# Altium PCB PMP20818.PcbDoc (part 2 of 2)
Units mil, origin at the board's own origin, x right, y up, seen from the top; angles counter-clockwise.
Board outline 3200 x 3200 mil, 4 copper layers (Top Layer, Signal Layer 1, Signal Layer 2, Bottom Layer), stack 61.2 mil thick; 130 components, 48 nets, 295 pads, 106 vias.
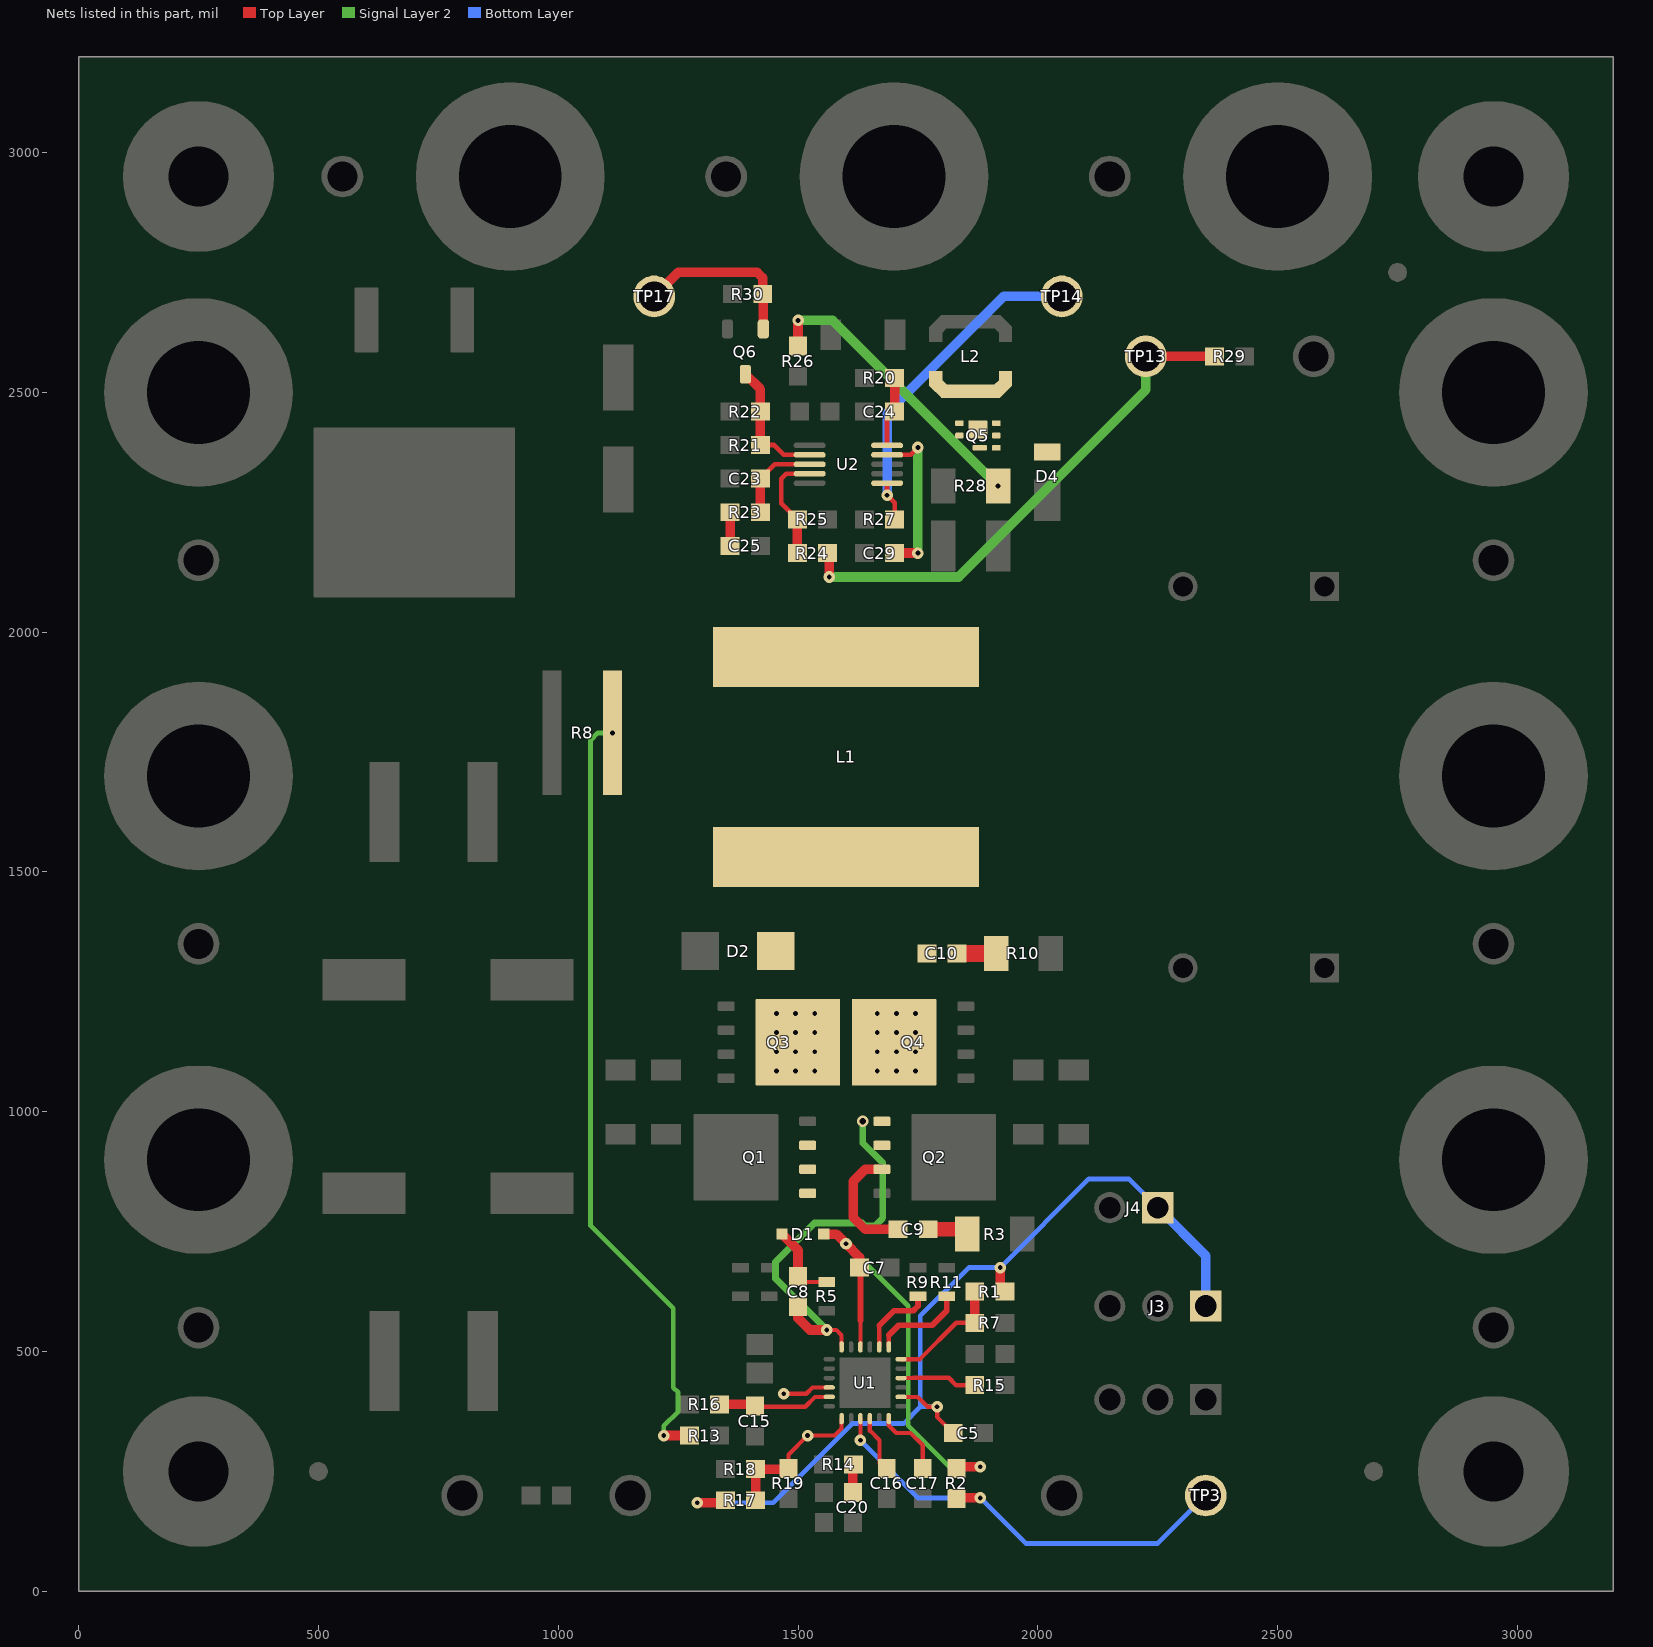
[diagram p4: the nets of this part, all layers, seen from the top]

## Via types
v1: diameter 24, hole 10, Top Layer to Bottom Layer, 69 vias
v2: diameter 24, hole 10, Top Layer to Bottom Layer, tented both sides, 27 vias
v3: diameter 24, hole 14, Top Layer to Bottom Layer, 5 vias
v4: diameter 20, hole 10, Top Layer to Bottom Layer, 5 vias

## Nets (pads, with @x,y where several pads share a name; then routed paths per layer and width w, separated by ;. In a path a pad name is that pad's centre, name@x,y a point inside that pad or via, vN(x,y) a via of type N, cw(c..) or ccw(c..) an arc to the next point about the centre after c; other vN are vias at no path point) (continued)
LO: R9.1 U1.8 | length 162
  Top Layer w9: U1.8@1669.53,509.8 1669.53,554.53
  Top Layer w12: 1669.53,554.53 1700,585 1740,585 1750,595 R9.1@1750,615
LOL: R11.2 U1.7 | length 196.2
  Top Layer w9: U1.7@1689.21,509.8 1689.21,534.21
  Top Layer w12: 1689.21,534.21 1710,555 1780,555 1810,585 R11.2@1810,615
NetC8_1: C8.1 D1.1 R5.2 | length 167.1
  Top Layer w9: C8.1@1500,656.5 1511.5,645 R5.2@1560,645
  Top Layer w20: D1.1@1466.69,745 1500,711.69 C8.1@1500,656.5
NetC9_1: C9.1 R3.1 | length 85.6
  Top Layer w30: C9.1@1771.5,755 1842.91,755 R3.1@1852.91,745
NetC10_2: C10.2 R10.2 | length 85.6
  Top Layer w35: C10.2@1834.43,1330 R10.2@1912.91,1330 ; R10.2@1902.91,1330 R10.2@1907.91,1335
NetC20_1: C20.1 R14.1 | length 57
  Top Layer w20: C20.1@1614.45,206.5 R14.1@1614.45,263.5
NetC23_1: C23.1 R23.2 U2.3 | length 185.2
  Top Layer w10: C23.1@1421.5,2320 1451.5,2350 U2.3@1524.29,2350
  Top Layer w20: R23.2@1421.5,2250 C23.1@1421.5,2320
NetC24_1: C24.1 R20.1 U2.10 | length 147.2
  Top Layer w10: U2.10@1685.71,2389.37 1685.71,2444.21 C24.1@1701.5,2460
  Top Layer w20: C24.1@1701.5,2460 R20.1@1701.5,2530
NetC25_1: C25.1 R23.1 | length 70
  Top Layer w20: C25.1@1358.5,2180 R23.1@1358.5,2250
NetD4_2: D4.2 L2.2 Q5.1 Q5.2 Q5.5 Q5.6 Q5.8
NetL1_2: L1.2 R8.1 R13.2 | length 1643.4
  Top Layer w20: v2(1220,325) R13.2@1273.5,325
  Signal Layer 2 w10: v1(1112.99,1790) 1082.37,1790 1067.37,1775 1067.37,762.63 1240,590 1240,425 1250,415 1250,375 1220,345 v2(1220,325)
NetQ5_4: Q5.4 Q5.7 R26.2 R28.2 | length 613.5
  Top Layer w20: R26.2@1500,2596.5 v2(1500,2650)
  Signal Layer 2 w20: v2(1500,2650) 1572.09,2650 v2(1917.09,2305)
NetQ6_1: Q6.1 R30.2 TP17.1 | length 357
  Top Layer w20: TP17.1@1200,2700 1250,2750 1415,2750 1426.5,2738.5 R30.2@1426.5,2705 ; Q6.1@1427.72,2632.24 R30.2@1427.72,2703.78
NetR17_2: R17.2 R18.1 R19.2 U1.19 | length 316.6
  Top Layer w9: R19.2@1478.5,255 R19.2@1480,256.5 1480,285 v2(1520,325) 1576.14,325 1590.79,339.65 U1.19@1590.79,360.2
  Top Layer w20: R17.2@1411.5,190 R18.1@1411.5,255 R19.2@1478.5,255
NetR24_1: R24.1 R29.2 TP13.1 | length 1086.5
  Top Layer w20: R24.1@1561.5,2165 1565,2161.5 v2(1565,2115) ; TP13.1@2225,2575 R29.2@2368.5,2575
  Signal Layer 2 w20: v2(1565,2115) 1835,2115 2225,2505 TP13.1@2225,2575
NetR24_2: R24.2 R25.2 U2.4 | length 232.4
  Top Layer w10: R25.2@1498.5,2235 1465,2268.5 1465,2320 1475.32,2330.32 U2.4@1524.29,2330.32
  Top Layer w20: R24.2@1498.5,2165 R25.2@1498.5,2235
OSC: R1.2 R7.1 U1.6 | length 250.1
  Top Layer w9: U1.6@1714.8,484.21 1754.21,484.21 1830,560 R7.1@1868.5,560
  Top Layer w20: R7.1@1868.5,560 R1.2@1868.5,625
PG: R2.2 TP3.1 U1.21 | length 946.4
  Top Layer w9: v2(1630,315) 1630,325 1630.16,325.16 U1.21@1630.16,360.2
  Top Layer w20: R2.2@1830,193.5 1831.5,195 v2(1880,195)
  Bottom Layer w10: v2(1630,315) 1750,195 v2(1880,195) 1975,100 2250,100 TP3.1@2350,200
RES: C17.1 U1.24 | length 150.6
  Top Layer w9: U1.24@1689.21,360.2 1689.21,345.79 1704.63,330.37 1734.63,330.37 1760,305 C17.1@1760,256.5
RT: R15.2 U1.4 | length 186.4
  Top Layer w9: U1.4@1714.8,444.84 1740,444.84 ; 1745.16,444.84 1740,444.84 ; R15.2@1853.5,444.84 R15.2@1868.35,430 1829.66,430 1814.13,445.53 1740.69,445.53 1740,444.84
SS: C16.1 U1.22 | length 116.2
  Top Layer w9: U1.22@1649.84,360.2 1649.84,335.16 1670,315 1670,266.5 C16.1@1680,256.5
SW: C8.2 C9.2 C10.1 D2.1 L1.1 Q1.1 Q1.2 Q1.3 Q2.1 Q2.2 Q2.3 Q3.5 Q3.6 Q3.7 Q3.8 Q3.9@1499.57,1145 Q4.5 Q4.6 Q4.7 Q4.8 Q4.9@1700.43,1145 U1.12 | length 1074.5
  Top Layer w9: v2(1560,545) 1580,545 1590.79,534.21 U1.12@1590.79,509.8
  Top Layer w20: C8.2@1500,593.5 1500,570.02 1525.02,545 v2(1560,545) ; Q2.3@1674.96,880 1640,880 1615,855 1615,780 1640,755 C9.2@1708.5,755
  Signal Layer 2 w14: v2(1560,545) 1452.91,652.09 1452.91,686.97 1534.06,768.13 1633.87,768.13 1639.87,762.13 1660.13,762.13 1676.87,778.87 1676.87,893.13 1635,935 v3(1635,980)
  other v1: 1455,1085 1495,1085 1535,1085 1665,1085 1705,1085 1745,1085 1455,1125 1495,1125 1535,1125 1665,1125 1705,1125 1745,1125 1455,1165 1495,1165 1535,1165 1665,1165 1705,1165 1745,1165 1455,1205 1495,1205 1535,1205 1665,1205 1705,1205 1745,1205
SYNC: R27.1 TP14.1 U2.6 | length 718.6
  Top Layer w10: U2.6@1685.71,2310.63 v2(1685.71,2285.49) 1701.5,2269.7 R27.1@1701.5,2235
  Bottom Layer w20: v2(1685.71,2285.49) 1685.71,2457.01 1928.7,2700 TP14.1@2050,2700
UVLO: Q6.3 R21.1 R22.2 U2.2 | length 271.9
  Top Layer w10: R21.1@1421.5,2390 1450,2390 1470.31,2369.69 U2.2@1524.29,2369.69
  Top Layer w20: Q6.3@1390.31,2537.76 1421.5,2506.57 R22.2@1421.5,2460 R21.1@1421.5,2390
VCC: C7.2 D1.2 R2.1 U1.10 | length 953.2
  Top Layer w9: U1.10@1630.16,509.8 1630.16,564.84
  Top Layer w12: C7.2@1628.5,675 1630.16,673.35 1630.16,564.84
  Top Layer w20: D1.2@1553.31,745 1580,745 v2(1600,725) 1628.5,696.5 C7.2@1628.5,675 ; R2.1@1830,256.5 1833.5,260 v2(1880,260)
  Signal Layer 2 w10: v2(1600,725) 1730,595 1730,345 1815,260 v2(1880,260)
VCC1: C29.1 U2.9 | length 339.1
  Top Layer w10: U2.9@1685.71,2369.69 1734.69,2369.69 v2(1750,2385)
  Top Layer w20: C29.1@1701.5,2165 v2(1750,2165)
  Signal Layer 2 w20: v2(1750,2165) v2(1750,2385)
VCCX: U1.16 | length 107.9
  Top Layer w9: v2@1473,412 1470,415 v2(1470,411.87) 1516.87,411.87 ; 1517,412 1530.16,425.16 U1.16@1565.2,425.16
VDDA: C5.2 J3.1 J4.1 R1.1 R17.1 U1.2 | length 1924
  Top Layer w9: U1.2@1714.8,405.47 1749.53,405.47 1770,385 v2(1790,385) 1790,363.5 C5.2@1823.5,330 ; R1.1@1921.5,635 R1.1@1931.5,625
  Top Layer w20: v1(1290,185) 1343.5,185 R17.1@1348.5,190 ; R1.1@1921.5,635 v2(1921.5,675)
  Bottom Layer w10: v1(1290,185) 1447.95,185 1612.95,350 1720,350 1755,385 ; v2(1790,385) 1755,385 ; J4.1@2250,800 2190,860 2106.5,860 v2(1921.5,675) 1855.75,675 1755,574.25 1755,385
  Bottom Layer w20: J4.1@2250,800 2350,700 J3.1@2350,595
VO_IC: C15.1 R16.1 U1.17 | length 235.4
  Top Layer w9: C15.1@1410,396.5 1421.5,385 1515,385 1535.47,405.47 U1.17@1565.2,405.47
  Top Layer w20: R16.1@1336.5,390 C15.1@1403.5,390
pads on no net: FID1.1 FID2.1 FID3.1 H1.1 H2.1 H3.1 H4.1 LBL1.0 Q1.9@1354.88,847.91 Q1.9@1354.88,905 Q1.9@1354.88,962.09 Q1.9@1388.35,905 Q1.9@1424.96,847.91 Q1.9@1424.96,905 Q1.9@1424.96,962.09 Q2.9@1770.04,847.91 Q2.9@1770.04,905 Q2.9@1770.04,962.09 Q2.9@1806.65,905 Q2.9@1840.12,847.91 Q2.9@1840.12,905 Q2.9@1840.12,962.09 Q3.9@1445.04,1087.91 Q3.9@1445.04,1145 Q3.9@1445.04,1202.09 Q3.9@1481.65,1145 Q3.9@1515.12,1087.91 Q3.9@1515.12,1145 Q3.9@1515.12,1202.09 Q4.9@1684.88,1087.91 Q4.9@1684.88,1145 Q4.9@1684.88,1202.09 Q4.9@1718.35,1145 Q4.9@1754.96,1087.91 Q4.9@1754.96,1145 Q4.9@1754.96,1202.09 Q5.0

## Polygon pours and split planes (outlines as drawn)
50VIN on Signal Layer 2 "Signal Layer2-VIN" (solid, remove dead copper, pour order 168): 2265,1005 2265,837.73 1785,837.73 1785,1005
50VIN on Signal Layer 2 "Signal Layer2-VIN" (solid, remove dead copper, pour order 166): 1455,1005 1455,835.84 1080,835.84 1080,1005
SW on Signal Layer 2 "SignalLayer2-SW" (solid, remove dead copper, pour order 170): 1791.2,1245 1791.2,1075 1406.2,1075 1406.2,1245
GND on Signal Layer 2 "Signal Layer2-GND" (solid, pour order 172): 0,3200 0,0 3200,0 3200,3200
50VIN on Signal Layer 1 "Signal Layer1-VIN" (solid, remove dead copper, pour order 160): 2280,1010 2280,835 1075,835 1075,1010
GND on Signal Layer 1 "Signal Layer1-GND" (solid, pour order 164): 0,3200 0,0 3200,0 3200,3200
SW on Signal Layer 1 "SignalLayer1-SW" (solid, remove dead copper, pour order 162): 1792.5,1230 1792.5,1060 1407.5,1060 1407.5,1230
12VS on Bottom Layer "12VS_L04_P174" (solid, remove dead copper, pour order 174): 1200,3200 1200,2705 450,2705 450,3200
50VIN on Bottom Layer "50VIN_L04_P180" (solid, remove dead copper, pour order 180): 2700,1950 3200,1950 3200,1170 2700,1170
50VOUT on Bottom Layer "50VOUT_L04_P182" (solid, remove dead copper, pour order 182): 2698.75,2750 3198.75,2750 3198.75,1970 2698.75,1970
11VOUT on Bottom Layer "11VOUT_L04_P178" (solid, remove dead copper, pour order 178): 0,1950 500,1950 500,1200 0,1200
12VIN on Bottom Layer "12VIN_L04_P176" (solid, remove dead copper, pour order 176): 0,2750 326.38,2750 500,2576.38 500,1970 0,1970
GND on Bottom Layer "Bottom Layer-GND" (solid, pour order 188): 0,3200 0,0 3200,0 3200,3200
SW on Bottom Layer "BottomLayer-SW" (solid, remove dead copper, pour order 186): 1792.5,1240 1792.5,1060 1407.5,1060 1407.5,1240
50VIN on Bottom Layer "BottomLayer-Vin" (solid, remove dead copper, pour order 184): 1080,1020 1080,835 1740,835 2125,835 2125,1020
50VIN on Top Layer "50VIN_L01_P092" (solid, remove dead copper, pour order 92): 1466.3,1009.68 1466.3,806.57 1062.24,806.88 1062.24,1009.47 1062.76,1010
50VIN on Top Layer "50VIN_L01_P084" (solid, remove dead copper, pour order 84): 3200,2020 2720,2020 2700,2000 2700,1280 2625,1205 2505,1205 2405,1205 2310,1110 2190,990 2190,860 2605,860 2680,935 2945,1200 3200,1200
11VOUT on Top Layer "11VOUT_L01_P080" (solid, remove dead copper, pour order 80): 0,1980 1050,1980 1050,350 750,350 750,1765 500,1765 500,1400 350,1250 0,1250
12VS on Top Layer "12VS_L01_P069" (solid, remove dead copper, pour order 69): 450,3200 1125,3200 1125,2860 835,2570 585,2570 450,2705
12VIN on Top Layer "12VIN_L01_P076" (solid, remove dead copper, pour order 76): 0,2750 325,2750 498.62,2576.38 498.62,2506.38 498.62,2500 950,2500 950,2450 995.07,2404.93 995.07,2399.99 1260,2399.99 1260,2210 1050,2000 0,2000
50VOUT on Top Layer "50VOUT_L01_P086" (solid, remove dead copper, pour order 86): 1865,2240 1975,2240 1975,2325 2090,2325 2200,2325 2410,2535 2410,2685 3175,2685 3200,2685 3200,2050 3195,2045 2700,2045 2675,2020 2675,1280 2620,1225 2525,1225 2525,2020 2370,2175 2160,2175 2105,2120 1865,2120 1865,2242.99
NetQ5_4 on Top Layer "NETQ5_4_L01_P094" (solid, remove dead copper, pour order 94): 1865,2390 1950,2390 1950,2258.74 1865,2258.74
NetD4_2 on Top Layer "NETD4_2_L01_P096" (solid, remove dead copper, pour order 96): 1750,2560 1965,2560 2065,2460 2065,2345 1970,2345 1970,2405 1790,2405 1750,2445
12VIN on Top Layer "12VIN_L01_P078" (solid, remove dead copper, pour order 78): 1630,2700 1960,2700 1960,2585 1920,2585 1630,2585 1630,2657.4
50VIN on Top Layer "Top Layer-VIN" (solid, remove dead copper, pour order 110): 1725.63,1010 2280,1010 2280,835 2185,835 2080,730 2071.58,721.58 1939.52,721.58 1939.93,810 1725.63,810
GND on Top Layer "Top Layer-GND" (solid, remove dead copper, pour order 158): 0,3200 0,0 3200,0 3200,3200
SW on Top Layer "SW_L01_P104" (solid, remove dead copper, pour order 104): 2010,1625 2010,1400 1785,1400 1785,1025 1700,1025 1700,815 1495,815 1495,1025 1415,1025 1415,1400 1190,1400 1190,1625
NetL1_2 on Top Layer "NETL1_2_L01_P106" (solid, remove dead copper, pour order 106): 2010,2090 1175,2090 1065,1980 1065,1650 2010,1650

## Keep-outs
Keep-Out Layer:
  the board outline again, w7
  text ".Layer_Name" at 577,-858.49 h60

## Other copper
Top Layer:
  text ".Layer_Name" at 577,-858.49 h60
Signal Layer 1:
  text ".layer_Name" at 577,-858.49 h40
Signal Layer 2:
  text ".layer_Name" at 577,-858.49 h40
Bottom Layer:
  rectangle net 50VOUT: 2525,1980 3050,2200
  rectangle net 50VOUT: 2525,1200 2670,2200
  text ".Layer_Name" at 577,-858.49 h60

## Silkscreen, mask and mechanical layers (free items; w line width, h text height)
Top Overlay:
  region: 1305,119.99 1005,119.99 1005,19.99 1305,19.99
  text "-" at 950,44.99 h40
  text ".PRJ_Number" at 380,39.99 h60
  text ".PCB_Rev" at 875,40 h60
  text ".Layer_Name" at 577,-858.49 h60
Bottom Overlay:
  text ".Layer_Name" at 577,-858.49 h60
Top Paste:
  text ".Layer_Name" at 577,-858.49 h60
Bottom Paste:
  text ".Layer_Name" at 577,-858.49 h60
Top Solder:
  text ".Layer_Name" at 577,-858.49 h60
  text ".Layer_Name" at 577,-858.49 h60
Bottom Solder:
  text ".Layer_Name" at 577,-858.49 h60
Drill Guide:
  text ".Layer_Name" at 577,-858.49 h60
M1 Board Outline:
  the board outline again, w10
  text ".Layer_Name" at 577,-858.49 h60
M2 Board Dimensions:
  rectangle: 0,-275 125,-150
  rectangle: 125,-400 500,-275
  lines w7: 0,-275 1000,-275 ; 125,-400 125,-150 ; 250,-400 250,-150 ; 500,-400 500,-150 ; 750,-400 750,-150 ; 0,-400 1000,-400 1000,-150 0,-150 0,-400
  text ".Layer_Name" at 577,-858.49 h60
M3 3D STEP Top:
  text ".Layer_Name" at 577,-858.49 h60
M4 3D STEP Bottom:
  text ".Layer_Name" at 577,-858.49 h60
M5 Assembly Top:
  lines w10: -292,-930.17 6308,-930.17 ; -292,-726.83 6310,-726.83 ; -292,-523.5 -292,-1133.5 3713,-1133.5 6310,-1133.5 6310,-523.5 -291.5,-523.5 -291.5,-1133.5 1284,-1133.5 ; 2173,-1133.5 2173,-523.5 ; 3440,-726.83 3440,-523.5 ; 4280,-726.83 4280,-523.5 ; 4902,-1140 4902,-937.17
  text "COMPONENTS MARKED 'DNP' SHOULD NOT BE POPULATED." at 1153.5,-318.5 h40
  text "ASSEMBLY VARIANT:" at 1153,-434 h40
  text ".VariantName" at 2189,-434 h40
  text "PCB VIEWED FROM TOP SIDE" at -228.5,-655.67 h60
  text "BOARD #:" at 2248,-655.67 h60
  text ".PRJ_Number" at 2793.5,-655.67 h60
  text "REV:" at 3638,-655.67 h60
  text ".PCB_Rev" at 3929.5,-655.67 h60
  text "SVN REV:" at 4476,-655.67 h60
  text ".VersionControl_RevNumber" at 4982,-655.67 h60
  text "TID #:" at 2248,-859 h60
  text ".TID" at 2793.5,-859 h60
  text "PLOT NAME =" at -228.5,-1064.34 h60
  text ".plot_File_Name" at 577,-1064.34 h60
  text "GENERATED    :" at 2250,-1064.34 h60
  text ".Print_Date" at 3119.5,-1064.34 h60
  text ".Print_Time" at 3848.5,-1064.34 h60
  text "TEXAS INSTRUMENTS" at 5113,-1064.34 h60
M6 Assembly Bottom:
  lines w10: -292.5,-727.33 6309.5,-727.33 ; -290.5,-930.67 6309.5,-930.67 ; 1115.5,-1140.5 1115.5,-937.67 ; 1737.5,-727.33 1737.5,-524 ; 2577.5,-727.33 2577.5,-524 ; 3844.5,-1134 3844.5,-524 ; 4733.5,-1134 6309,-1134 6309,-524 -292.5,-524 -292.5,-1134 2304.5,-1134 6309.5,-1134 6309.5,-524
  text "COMPONENTS MARKED 'DNP' SHOULD NOT BE POPULATED." at 6102,-318 h40
  text ".VariantName" at 5058,-434 h40
  text "ASSEMBLY VARIANT:" at 6097,-434 h40
  text ".VersionControl_RevNumber" at 1035.5,-656.17 h60
  text "SVN REV:" at 1541.5,-656.17 h60
  text ".PCB_Rev" at 2088,-656.17 h60
  text "REV:" at 2379.5,-656.17 h60
  text ".PRJ_Number" at 3224,-656.17 h60
  text "BOARD #:" at 3769.5,-656.17 h60
  text "PCB VIEWED FROM BOTTOM SIDE" at 6246,-656.17 h60
  text ".TID" at 3224,-859.5 h60
  text "TID #:" at 3769.5,-859.5 h60
  text "TEXAS INSTRUMENTS" at 904.5,-1064.84 h60
  text ".Print_Time" at 2169,-1064.84 h60
  text ".Print_Date" at 2898,-1064.84 h60
  text "GENERATED    :" at 3767.5,-1064.84 h60
  text ".plot_File_Name" at 5440.5,-1064.84 h60
  text "PLOT NAME =" at 6246,-1064.84 h60
M9 Title Sheet:
  drawing of 57 lines, arcs and shapes, not listed
  text "1" at 739.84,8036.5 h70
  text "2" at 3235.5,8036.5 h70
  text "3" at 5724.84,8036.5 h70
  text "4" at 8231.51,8036.5 h70
  text "5" at 10730.5,8036.5 h70
  text "6" at 13235.5,8036.5 h70
  text "A" at -416.5,6893.5 h70
  text "A" at 14383.5,6893.5 h70
  text "B" at -416.5,4513.5 h70
  text "B" at 14383.5,4513.5 h70
  text "C" at -416.5,2138.5 h70
  text "C" at 14383.5,2138.5 h70
  text "PROJECT TITLE:" at 11343.5,277.5 h45
  text ".PRJ_Title" at 11393.5,144.17 h70
  text "DESIGNED FOR:" at 11343.5,-23.5 h45
  text ".PRJ_Customer" at 11393.5,-163.5 h70
  text "D" at -416.5,-231.5 h70
  text "D" at 14383.5,-231.5 h70
  text "FILE NAME:" at 11343.5,-323.5 h45
  text ".PCB_File_Name_No_Path" at 11393.5,-443.5 h70
  text "Texas Instruments (TI) and/or its licensors do not warrant the accuracy or completeness of this specification" at 6374,-605.34 h45
  text "ENGINEER:" at 11343.5,-613.5 h45
  text "LAYOUT BY:" at 12848.5,-613.5 h45
  text "or any information contained therein. TI and/or its licensors do not warrant that this design will meet" at 6329.01,-718 h45
  text ".PRJ_Engineer" at 11393.5,-768.49 h70
  text ".PCB_Layout" at 12899,-768.49 h70
  text "the specifications, will be suitable for your application or fit for any particular purpose, or will operate in" at 6329.01,-830.67 h45
  text ".Layer_Name" at 577,-858.49 h60
  text "ALTIUM DESIGNER VERSION:" at 12848.5,-923.5 h45
  text "an implementation. TI and/or its licensors do not warrant that the design is production worthy. You should" at 6329.01,-943.33 h45
  text "completely validate and test your design implementation to confirm the system functionality for your application." at 6374,-1056 h45
  text ".print_Scale" at 11393.5,-1056.83 h70
  text ".Application_BuildNumber" at 12899,-1056.83 h70
  text "1" at 739.84,-1263.5 h70
  text "2" at 3235.5,-1263.5 h70
  text "3" at 5724.84,-1263.5 h70
  text "4" at 8231.51,-1263.5 h70
  text "5" at 10730.5,-1263.5 h70
  text "6" at 13235.5,-1263.5 h70
M10 Fab Notes:
  drawing of 185 lines, arcs and shapes, not listed
  text "DESIGN INFORMATION" at 12381.02,5910 h60
  text "MIN. TRACK WIDTH:" at 11736.46,5730 h60
  text "8" at 12832.7,5730 h60
  text "MIL" at 12987.46,5730 h60
  text "MIN. CLEARANCE:" at 11736.46,5598 h60
  text "0.2" at 12772.7,5598 h60
  text "mm" at 12987.46,5598 h60
  text "MIN. VIA PAD SIZE:" at 11736.46,5466 h60
  text "24" at 12802.71,5466 h60
  text "MIL" at 12987.46,5466 h60
  text "0.152mm (6MIL)" at 12431.46,5324.29 h60
  text "MINIMUM ANNULAR RING" at 11407.23,5320 h60
  text "EXTERNAL" at 13139.46,5320 h60
  text "PER" at 11607.23,5202 h60
  text "IPC-D-275 CLASS 2 LEVEL C" at 11827.23,5202 h60
  text "MIL, HOLES" at 13315.46,5089.71 h60
  text "+/-" at 12923,5089 h60
  text "+/-" at 13777,5089 h60
  text "REGISTRATION TOLERANCES:" at 11407.23,5084 h60
  text "METAL" at 12607,5084 h60
  text "5" at 13183.2,5084 h60
  text "3" at 14016.2,5084 h60
  text "MIL" at 14132.46,5084 h60
  text "MATERIAL:" at 11332.46,4874.54 h60
  text "FR-4 High Tg" at 12318.9,4734.21 h60
  text "FR-408" at 11753.46,4725.64 h60
  text "X" at 12165.46,4725.64 h60
  text "OTHER" at 13241.46,4725.64 h60
  text "62 MIL (1.6mm) +/-10%" at 12073.56,4562.92 h60
  text "THICKNESS:" at 11407.23,4558.64 h60
  text "X" at 11945.4,4558.64 h60
  text "OTHER" at 13358.46,4558.64 h60
  text "TOLERANCE:" at 11407.23,4400.64 h60
  text "X" at 12246.53,4400.64 h60
  text "ANSI IPC-6012 TYPE 3 CLASS 2" at 12433.48,4400.64 h60
  text "OTHER +/-" at 12433.46,4244.64 h60
  text "BOW & TWIST:" at 11407.23,4087.64 h60
  text "X" at 12246.53,4087.64 h60
  text "ANSI IPC-6012 TYPE 3 CLASS 2" at 12433.48,4087.64 h60
  text "OTHER +/-" at 12433.46,3929.13 h60
  text "DRILLING:" at 11332.46,3790.64 h60
  text "REFERENCE:" at 11407.23,3673.64 h60
  text "X" at 12055.46,3673.64 h60
  text "AS SHOWN" at 12242.46,3673.64 h60
  text "X" at 12956.46,3673.64 h60
  text "NC_DRILL FILES" at 13093.46,3673.64 h60
  text "PTH MIN COPPER THICKNESS:" at 11407.23,3515.64 h60
  text "X" at 12757.46,3515.64 h60
  text "1MIL" at 12894.46,3515.64 h60
  text "OTHER" at 13391.46,3515.64 h60
  text "BOARD FINISH:" at 11332.46,3356.64 h60
  text "SILKSCREEN:" at 11487.68,3238.64 h60
  text "X" at 12436.46,3238.64 h60
  text "TOP" at 12562.46,3238.64 h60
  text "X" at 12946.46,3238.64 h60
  text "BOTTOM" at 13073.46,3238.64 h60
  text "SILKSCREEN COLOR:" at 11487.68,3071.64 h60
  text "X" at 12435.42,3071.64 h60
  text "WHITE" at 12562.46,3071.64 h60
  text "OTHER" at 13073.46,3071.64 h60
  text "SOLDER RESIST COLOR:" at 11487.68,2901.64 h60
  text "X" at 12055.42,2742.44 h60
  text "GREEN" at 12182.46,2742.44 h60
  text "BLUE" at 12773.46,2742.44 h60
  text "OTHER" at 13311.46,2742.44 h60
  text "IMMERSION GOLD (ENIG)" at 12393.46,2553.92 h60
  text "ENEPIG" at 13731,2550.64 h60
  text "SURFACE FINISH:" at 11332.46,2549.64 h60
  text "X" at 12206.51,2549.64 h60
  text "IMM. TIN/SILVER OR EQUIV" at 11662,2392.64 h60
  text "OTHER" at 13093.46,2392.64 h60
  text "ARRAY/PANEL:" at 11332.46,2213.64 h60
  text "CUT AND TRIM PER MECH LAYER 1" at 12393.46,2209.35 h60
  text "X" at 12205,2205 h60
  text "N.C. ROUTE" at 12393.46,2057.64 h60
  text "V. SCORE" at 13259.46,2057.64 h60
  text "CERTIFICATION:" at 11332.46,1920.64 h60
  text "MATERIALS AND WORKMANSHIP FOR ALL PCBS" at 12057.46,1920.64 h60
  text "TO MEET OR EXCEED THE REQUIREMENTS OF:" at 12057.46,1822.64 h60
  text "X" at 11683.96,1686.13 h60
  text "ANSI IPC-A-600F CLASS ->" at 11822.96,1686.13 h60
  text "X" at 13462.02,1686.13 h60
  text "2" at 13580.96,1686.14 h60
  text "1" at 13265.96,1684.64 h60
  text "3" at 13934.96,1684.64 h60
  text "X" at 11686.02,1526.64 h60
  text "UL 94V-0" at 11822.96,1526.64 h60
  text "X" at 12498.02,1526.64 h60
  text "RoHS" at 12634.96,1526.64 h60
  text "OTHER" at 13279.36,1526.64 h60
  text "PER ORDER" at 13676.42,1526.64 h60
  text "ADDITIONAL REQUIREMENTS:" at 11332.46,1385.64 h60
  text "MICROSECTION:" at 11407.23,1270.64 h60
  text "YES" at 12312.96,1270.64 h60
  text "REQUIRED" at 13174.46,1114.49 h60
  text "BARE BOARD ELEC. TEST:" at 11407.23,1111.64 h60
  text "NONE" at 12712.96,1111.64 h60
  text "PER ORDER" at 13766.46,1111.64 h60
  text "X" at 13640,1110 h60
  text "MANUFACTURER'S UL:" at 11407.23,954.64 h60
  text "RAIL" at 12572.96,950.35 h60
  text "METAL" at 13064.77,950.35 h60
  text "X" at 13440,950 h60
  text "SILK" at 13576.46,950.35 h60
  text ".Layer_Name" at 577,-858.49 h60
M11 Gerber Information:
  lines w10: -292,-930.17 6308,-930.17 ; -292,-726.83 6310,-726.83 ; -292,-523.5 -292,-1133.5 3713,-1133.5 6310,-1133.5 6310,-523.5 -291.5,-523.5 -291.5,-1133.5 1284,-1133.5 ; 2173,-1133.5 2173,-523.5 ; 3440,-726.83 3440,-523.5 ; 4280,-726.83 4280,-523.5 ; 4902,-1140 4902,-937.17
  text "ALL ARTWORK VIEWED FROM TOP SIDE" at -228.5,-655.67 h60
  text "BOARD #:" at 2248,-655.67 h60
  text ".PRJ_Number" at 2793.5,-655.67 h60
  text "REV:" at 3638,-655.67 h60
  text ".PCB_Rev" at 3929.5,-655.67 h60
  text "SVN REV:" at 4476,-655.67 h60
  text ".VersionControl_RevNumber" at 4982,-655.67 h60
  text "LAYER NAME =" at -228.5,-858.49 h60
  text "TID #:" at 2248,-859 h60
  text ".TID" at 2793.5,-859 h60
  text "PLOT NAME =" at -228.5,-1064.34 h60
  text ".plot_File_Name" at 577,-1064.34 h60
  text "GENERATED    :" at 2250,-1064.34 h60
  text ".Print_Date" at 3119.5,-1064.34 h60
  text ".Print_Time" at 3848.5,-1064.34 h60
  text "TEXAS INSTRUMENTS" at 5113,-1064.34 h60
M12 Stackup:
  drawing of 295 lines, arcs and shapes, not listed
  text "Layer" at 9905.59,7543.12 h40
  text "Name" at 10185.53,7543.12 h40
  text "Material" at 10818.69,7543.12 h40
  text "Thickness" at 11398.54,7543.12 h40
  text "Constant" at 11838.43,7543.12 h40
  text "Board Layer Stack" at 12225,7543.12 h40
  text "1" at 9905.59,7463.12 h40
  text "Top Overlay" at 10185.53,7463.12 h40
  text "2" at 9905.59,7383.12 h40
  text "Top Solder" at 10185.53,7383.12 h40
  text "Solder Resist" at 10818.69,7383.12 h40
  text "0.40mil" at 11398.54,7383.12 h40
  text "3.5" at 11838.43,7383.12 h40
  text "3" at 9905.59,7303.12 h40
  text "Top Layer" at 10185.53,7303.12 h40
  text "Copper" at 10818.69,7303.12 h40
  text "2.80mil" at 11398.54,7303.12 h40
  text "4" at 9905.59,7223.12 h40
  text "Dielectric1" at 10185.53,7223.12 h40
  text "FR-4" at 10818.69,7223.12 h40
  text "16.00mil" at 11398.54,7223.12 h40
  text "4.8" at 11838.43,7223.12 h40
  text "5" at 9905.59,7143.12 h40
  text "Signal Layer 1" at 10185.53,7143.12 h40
  text "Copper" at 10818.69,7143.12 h40
  text "2.80mil" at 11398.54,7143.12 h40
  text "6" at 9905.59,7063.12 h40
  text "Dielectric 3" at 10185.53,7063.12 h40
  text "18.00mil" at 11398.54,7063.12 h40
  text "4.2" at 11838.43,7063.12 h40
  text "7" at 9905.59,6983.12 h40
  text "Signal Layer 2" at 10185.53,6983.12 h40
  text "Copper" at 10818.69,6983.12 h40
  text "2.80mil" at 11398.54,6983.12 h40
  text "8" at 9905.59,6903.12 h40
  text "Dielectric 2" at 10185.53,6903.12 h40
  text "FR-4" at 10818.69,6903.12 h40
  text "16.00mil" at 11398.54,6903.12 h40
  text "4.2" at 11838.43,6903.12 h40
  text "9" at 9905.59,6823.12 h40
  text "Bottom Layer" at 10185.53,6823.12 h40
  text "Copper" at 10818.69,6823.12 h40
  text "2.80mil" at 11398.54,6823.12 h40
  text "10" at 9905.59,6743.12 h40
  text "Bottom Solder" at 10185.53,6743.12 h40
  text "Solder Resist" at 10818.69,6743.12 h40
  text "0.40mil" at 11398.54,6743.12 h40
  text "3.5" at 11838.43,6743.12 h40
  text "11" at 9905.59,6663.12 h40
  text "Bottom Overlay" at 10185.53,6663.12 h40
  text ".Layer_Name" at 577,-858.49 h60
M13 Component Bodies Top:
  text ".Layer_Name" at 577,-858.49 h60
M14 Component Bodies Bottom:
  text ".Layer_Name" at 577,-858.49 h60
M15 Courtyards Top:
  text ".Layer_Name" at 577,-858.49 h60
M16 Courtyards Bottom:
  text ".Layer_Name" at 577,-858.49 h60
Drill Drawing:
  circle w10: c3658.85,836.24 r18.42
  lines w10: 3640.44,909.91 3649.64,909.91 3658.85,900.7 3668.06,909.91 3677.27,909.91 3668.06,919.12 3677.27,928.33 3668.06,928.33 3658.85,937.54 3649.64,928.33 3640.44,928.33 3649.64,919.12 3640.44,909.91 ; 3640.44,1066.46 3658.85,1075.67 3677.27,1066.46 3668.06,1084.88 3677.27,1103.3 3658.85,1094.09 3640.44,1103.3 3649.64,1084.88 3640.44,1066.46 ; 3640.44,1149.34 3658.85,1158.55 3677.27,1149.34 3668.06,1167.76 3677.27,1186.18 3658.85,1176.97 3640.44,1186.18 3649.64,1167.76 3640.44,1149.34 ; 3640.44,1269.06 3677.27,1269.06 3658.85,1232.22 3640.44,1269.06 ; 3640.44,1315.1 3640.44,1324.31 3649.64,1333.52 3640.44,1342.73 3640.44,1351.94 3649.64,1351.94 3658.85,1342.73 3668.06,1351.94 3677.27,1351.94 3677.27,1342.73 3668.06,1333.52 3677.27,1324.31 3677.27,1315.1 3668.06,1315.1 3658.85,1324.31 3649.64,1315.1 3640.44,1315.1 ; 3647.8,913.6 3653.33,913.6 3658.85,908.07 3664.38,913.6 3669.9,913.6 3664.38,919.12 3669.9,924.65 3664.38,924.65 3658.85,930.17 3653.33,924.65 3647.8,924.65 3653.33,919.12 3647.8,913.6 ; 3647.8,1073.83 3658.85,1079.36 3669.9,1073.83 3664.38,1084.88 3669.9,1095.93 3658.85,1090.41 3647.8,1095.93 3653.33,1084.88 3647.8,1073.83 ; 3647.8,1322.47 3647.8,1328 3653.33,1333.52 3647.8,1339.05 3647.8,1344.57 3653.33,1344.57 3658.85,1339.05 3664.38,1344.57 3669.9,1344.57 3669.9,1339.05 3664.38,1333.52 3669.9,1328 3669.9,1322.47 3664.38,1322.47 3658.85,1328 3653.33,1322.47 3647.8,1322.47
  lines w12: 3606,792.96 4924.68,792.96 ; 3606,1373.12 4924.68,1373.12 ; 3831.24,710.08 3831.24,1456 ; 4052.58,710.08 4052.58,1456 ; 4476.95,710.08 4476.95,1456 ; 4649.71,710.08 4649.71,1456 ; 3606,710.08 4924.68,710.08 4924.68,1456 3606,1456 3606,710.08
  text "Symbol" at 3655.73,1397.98 h48
  text "Quantity" at 3856.11,1397.98 h48
  text "Finished Hole Size" at 4077.44,1397.98 h48
  text "Plated" at 4501.81,1397.98 h48
  text "Hole Type" at 4674.57,1397.98 h48
  text "101" at 3856.11,1315.1 h40
  text "10.00mil (0.254mm)" at 4077.44,1315.1 h40
  text "PTH" at 4501.81,1315.1 h40
  text "Round" at 4674.57,1315.1 h40
  text "5" at 3856.11,1232.22 h40
  text "14.00mil (0.356mm)" at 4077.44,1232.22 h40
  text "PTH" at 4501.81,1232.22 h40
  text "Round" at 4674.57,1232.22 h40
  text "4" at 3856.11,1149.34 h40
  text "41.34mil (1.050mm)" at 4077.44,1149.34 h40
  text "PTH" at 4501.81,1149.34 h40
  text "Round" at 4674.57,1149.34 h40
  text "8" at 3856.11,1066.46 h40
  text "45.28mil (1.150mm)" at 4077.44,1066.46 h40
  text "PTH" at 4501.81,1066.46 h40
  text "Round" at 4674.57,1066.46 h40
  text "17" at 3856.11,983.58 h40
  text "63.00mil (1.600mm)" at 4077.44,983.58 h40
  text "PTH" at 4501.81,983.58 h40
  text "Round" at 4674.57,983.58 h40
  text "B" at 3636.58,973.59 h36.84
  text "4" at 3856.11,900.7 h40
  text "125.98mil (3.200mm)" at 4077.44,900.7 h40
  text "PTH" at 4501.81,900.7 h40
  text "Round" at 4674.57,900.7 h40
  text "9" at 3856.11,817.82 h40
  text "214.57mil (5.450mm)" at 4077.44,817.82 h40
  text "PTH" at 4501.81,817.82 h40
  text "Round" at 4674.57,817.82 h40
  text "148 Total" at 3856.11,734.94 h40
  text ".Layer_Name" at 577,-858.49 h60

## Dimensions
0,-400 to 1000,-400 on M2 Board Dimensions
-10,0 to 0,3200 on M2 Board Dimensions
0,-10 to 3200,0 on M2 Board Dimensions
